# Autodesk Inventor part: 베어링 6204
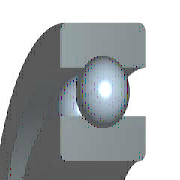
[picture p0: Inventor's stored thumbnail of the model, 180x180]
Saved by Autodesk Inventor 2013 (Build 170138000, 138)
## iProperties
IsCustomPart: 0
Created: 2015-12
Part Number: 베어링 6204
Material: 강철, 연강
Description: 깊은 그루브 볼 베어링
Document SubType Name: Modeling
Standard: KS B 2023
Designer: mdu
Standards Organization: KS
Language: ko-KR
Size Designation: 6204 - 20 x 47 x 14
Categories: <MemberInstance><Categories><Category DisplayName="샤프트 부품" InternalName="7f7aeb1f-a693-4053-b835-cee3144e0d98" Mnemonic="SHFT"><Category DisplayName="베어링" Inter
Density: 7.86 g/cm^3
Mass: 104.255 g
Surface Area: 87.8912 cm^2
Volume: 13.264 cm^3
Author: mud
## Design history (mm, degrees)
sketch "스케치" dims "d0" = 7.02 (= -0.26 x WD + 0.26 x BD)
  geometry: L1 (3.49, 16.75)-(10.51, 16.75); L2 (7, 16.75)-(7, 13.24); L3 (7, 16.75)-(7, 20.26); L4 (4.392, 14.401)-(0, 14.401); L5 (0, 10)-(14, 10); L6 (4.392, 19.099)-(0, 19.099); L7 (0, 23.5)-(14, 23.5); L8 (14, 10)-(14, 14.401); L9 (9.608, 14.401)-(14, 14.401); L10 (9.608, 19.099)-(14, 19.099); L11 (14, 23.5)-(14, 19.099); L12 (-1.4, 0)-(8.4, 0) reference; L13 (0, -0.3)-(0, 5.3) reference
  constraints: 22 end point, 4 point on line, 2 collinear, 2 perpendicular, 2 symmetric about line, 1 midpoint, 1 parallel, 14 other
  dimensions: "d9" = 20 diameter of L5 L12 (= WD); "d11" = 47 diameter of L7 L12 (= BD); "d12" = 14 distance between parallel lines of L8 L13 (= KB); "d13" = 28.802 diameter of L9 L12 (= 0.326 x BD + 0.674 x WD)
revolve "본체" stored, may be unused: angle "d6" = 90 deg
revolve "볼" stored, may be unused: angle "d7" = 90 deg
pattern_circular "IDS_ARRAYBALL[SIMPL:T]" dims angle "d3" = 360 deg
body "Solid1"
fillet "모깎기1" dims "d1" = 1 (= KRS)
other parameters: "WD" = 20 [user parameter; used in 5 equation terms], "BD" = 47 [user parameter; used in 5 equation terms], "KB" = 14 [user parameter; used in 1 equation term], "KRS" = 1 [user parameter; used in 1 equation term], "d4" = 0, "d5" = 0, "d8" = 0, "d14" = 0, "d15" = 0, "BBA" = 0 [user parameter], "BC0" = 6550000 [user parameter], "BC" = 1.27e+07 [user parameter], "BR" = 23.5 (= 0.5 x BD) [user parameter]
